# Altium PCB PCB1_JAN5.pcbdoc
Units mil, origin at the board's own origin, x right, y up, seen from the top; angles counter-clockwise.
Board outline 1805 x 855 mil, 2 copper layers (Top Layer, Bottom Layer); 70 components, 53 nets, 260 pads, 40 vias.
Unrouted connection lines stored in the file: 8.
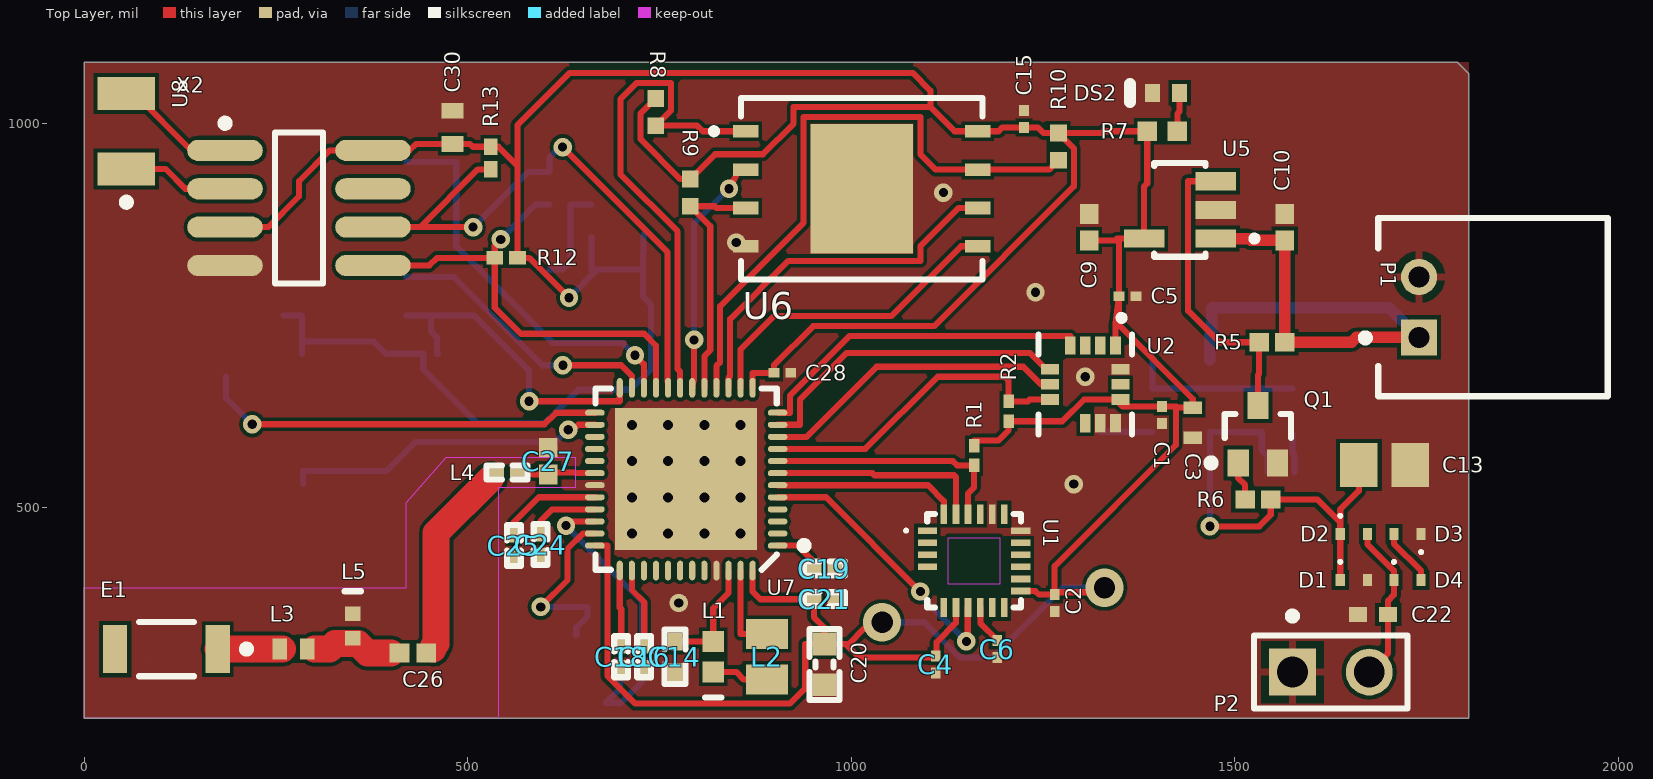
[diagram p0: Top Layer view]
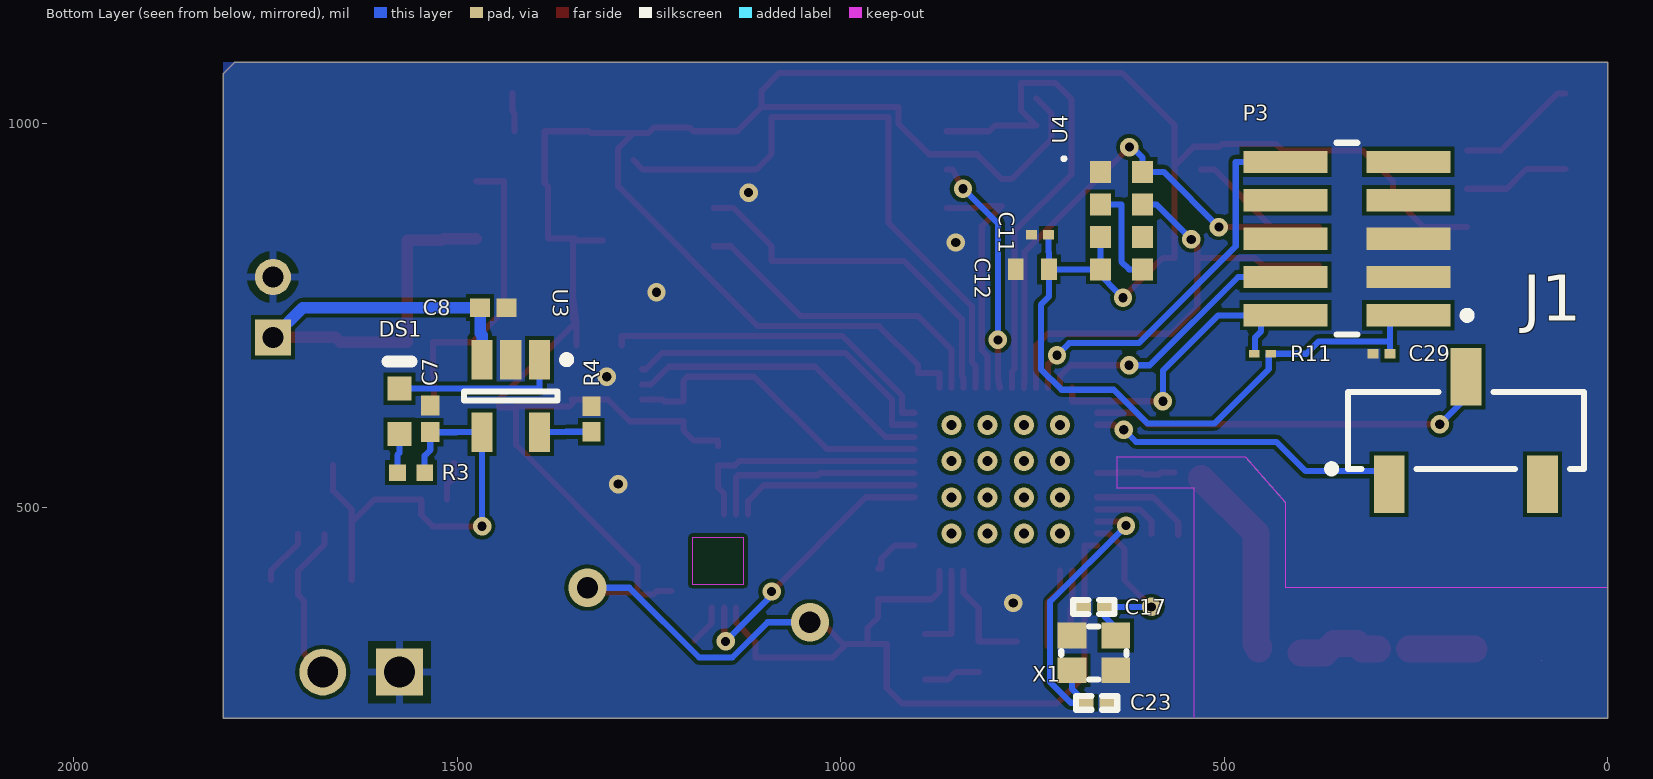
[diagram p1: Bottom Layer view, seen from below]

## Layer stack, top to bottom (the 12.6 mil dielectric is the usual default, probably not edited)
Top Solder: solder mask 0.4, Solder Resist, Dk 3.5
Top Layer: signal copper 1.4
Dielectric 1: dielectric 12.6, FR-4, Dk 4.8
Bottom Layer: signal copper 1.4
Bottom Solder: solder mask 0.4, Solder Resist, Dk 3.5

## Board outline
0,225 0,1080 1790,1080 1805,1065 1805,225
cut-out: 86.74,300.19

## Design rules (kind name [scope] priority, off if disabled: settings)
Clearance CPWG [InNet('RF')] p1: gap=5 ignorepadtopadclearanceinfootprint=TRUE // RF
Clearance [All] p2: gap=5 ignorepadtopadclearanceinfootprint=TRUE except(10: Via-Via)
HoleSize [All] p1: absolutevalues=TRUE maxlimit=100 minlimit=0.6 maxpercent=80.000 minpercent=20.000
MinimumSolderMaskSliver [All] p1: minsoldermaskwidth=5
PolygonConnect PolygonConnect_5 [All vs IsNamedPolygon('Top Layer-GND')] p1: thpad.connectstyle=Relief thpad.reliefconductorwidth=10 thpad.reliefentries=4 thpad.polygonreliefangle="90 Angle" thpad.airgapwidth=10 smdpad.connectstyle=Direct smdpad.reliefconductorwidth=10 smdpad.reliefentries=4 smdpad.polygonreliefangle="90 Angle" smdpad.airgapwidth=10 via.connectstyle=Direct via.reliefconductorwidth=10 via.reliefentries=4 via.polygonreliefangle="90 Angle" via.airgapwidth=10
PolygonConnect PolygonConnect_4 [All vs IsNamedPolygon('Bottom Layer-GND')] p2: thpad.connectstyle=Relief thpad.reliefconductorwidth=10 thpad.reliefentries=4 thpad.polygonreliefangle="90 Angle" thpad.airgapwidth=10 smdpad.connectstyle=Direct smdpad.reliefconductorwidth=10 smdpad.reliefentries=4 smdpad.polygonreliefangle="90 Angle" smdpad.airgapwidth=10 via.connectstyle=Direct via.reliefconductorwidth=10 via.reliefentries=4 via.polygonreliefangle="90 Angle" via.airgapwidth=10
PolygonConnect PolygonConnect_3 [All vs IsNamedPolygon('Top Layer-GND')] p3: thpad.connectstyle=Relief thpad.reliefconductorwidth=10 thpad.reliefentries=4 thpad.polygonreliefangle="90 Angle" thpad.airgapwidth=10 smdpad.connectstyle=Relief smdpad.reliefconductorwidth=10 smdpad.reliefentries=4 smdpad.polygonreliefangle="90 Angle" smdpad.airgapwidth=10 via.connectstyle=Direct via.reliefconductorwidth=10 via.reliefentries=4 via.polygonreliefangle="90 Angle" via.airgapwidth=10
PolygonConnect PolygonConnect_2 [All vs IsNamedPolygon('Bottom Layer-GND')] p4: thpad.connectstyle=Relief thpad.reliefconductorwidth=10 thpad.reliefentries=4 thpad.polygonreliefangle="90 Angle" thpad.airgapwidth=10 smdpad.connectstyle=Direct smdpad.reliefconductorwidth=10 smdpad.reliefentries=4 smdpad.polygonreliefangle="90 Angle" smdpad.airgapwidth=10 via.connectstyle=Relief via.reliefconductorwidth=10 via.reliefentries=4 via.polygonreliefangle="90 Angle" via.airgapwidth=10
PolygonConnect PolygonConnect_1 [All vs IsNamedPolygon('Top Layer-GND')] p5: thpad.connectstyle=Relief thpad.reliefconductorwidth=10 thpad.reliefentries=4 thpad.polygonreliefangle="90 Angle" thpad.airgapwidth=10 smdpad.connectstyle=Direct smdpad.reliefconductorwidth=10 smdpad.reliefentries=4 smdpad.polygonreliefangle="90 Angle" smdpad.airgapwidth=10 via.connectstyle=Relief via.reliefconductorwidth=10 via.reliefentries=4 via.polygonreliefangle="90 Angle" via.airgapwidth=10
PolygonConnect [All] p6: connectstyle=Relief reliefconductorwidth=10 reliefentries=4 polygonreliefangle="90 Angle" airgapwidth=10
RoutingVias [All] p1: holewidth=12 width=24 viastyle="Through Hole" minholewidth=12 minwidth=24 maxholewidth=12 maxwidth=24
SilkToSilkClearance [All] p1: silktosilkclearance=7
SilkToSolderMaskClearance [IsPad] p1: minsilkscreentomaskgap=5 clearancetoexposedcopper=TRUE
SolderMaskExpansion [All] p1: expansion=4
Width RF2 [InNet('NetE1_1')] p1: maxlimit=35 minlimit=35 preferedwidth=35 minimp=50.000000 maximp=50.000000 favimp=50.000000
Width RF1 [InNet('NetC26_1')] p2: maxlimit=35 minlimit=35 preferedwidth=35 minimp=50.000000 maximp=50.000000 favimp=50.000000
Width RF [InNet('RF')] p3: maxlimit=35 minlimit=35 preferedwidth=35 minimp=50.000000 maximp=50.000000 favimp=50.000000
Width VBAT [InNet('VBAT')] p4: maxlimit=15 minlimit=15 preferedwidth=15 minimp=50.000000 maximp=50.000000 favimp=50.000000
Width [All] p5: maxlimit=8 minlimit=8 preferedwidth=8 minimp=50.000000 maximp=50.000000 favimp=50.000000
26 further rules are at their usual default settings.

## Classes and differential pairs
component class "SimPL_IMU_v1_1 _JAN5": C14 C15 C16 C17 C18 C19 C20 C21 C23 C24 C25 C26 C27 C28 C29 C30 E1 J1 L1 L2 L3 L4 L5 P3 R8 R9 R10 R11 R12 R13 U6 U7 U8 X1 X2
component class SimPL_IMU_v1_0_JAN5: C1 C2 C3 C4 C5 C6 C7 C8 C9 C10 C11 C12 C13 C22 D1 D2 D3 D4 DS1 DS2 P1 P2 Q1 R1 R2 R3 R4 R5 R6 R7 U2 U3 U4 U5

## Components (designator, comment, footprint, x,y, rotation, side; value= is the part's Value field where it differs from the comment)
C1 "0.1uF" CAPC0603X33X15LL03T05 1405,620 r90 top
C2 "0.1uF" CAPC0603X33X15LL03T05 1265,375 r90 top
C3 "1.0uF" CAPC1005X70X10LL20T00 1445,610 r90 top
C4 "0.1uF" CAPC0603X33X15LL03T05 1110,295 r90 top
C5 "0.1uF" CAPC0603X33X15LL03T05 1360,775 r180 top
C6 "0.1uF" CAPC0603X33X15LL03T05 1190,315 r90 top
C7 "4.7uF" CAPC1005X55X25NL05T10 1535,615 r270 bottom
C8 "4.7uF" CAPC1005X55X25NL05T10 1452.68,760 r0 bottom
C9 "1uF" CAPC1005X55X25NL05T10 1310,865 r270 top
C10 "1uF" CAPC1005X55X25NL05T10 1565,865 r270 top
C11 "0.1uF" CAPC0603X33X15LL03T05 740,855 r180 bottom
C12 "2.2uF" CAPC1005X70X10NL20T00 750,810 r180 bottom
C13 "GRM21BR60J226ME39L" CAPC2013X140X45NL15T25 1695,555 r180 top
C14 "1.0µF" CAPC1005X04L 770,305 r90 top
C15 "0.1uF" CAPC0603X33X15LL03T05 1225,1006.02 r270 top
C16 "12pF" CAPC0603X03L 730,305 r90 top
C17 "12pF" CAPC0603X03L 670,370 r180 bottom
C18 "12pF" CAPC0603X03L 700,305 r90 top
C19 "100nF" CAPC0603X03L 965,420 r0 top
C20 "4.7µF" CAPC1608X06L 965,295 r270 top
C21 "100nF" CAPC0603X03L 965,380 r0 top
C22 "6.8nF" 0402 1680,360 r180 top
C23 "12pF" CAPC0603X03L 666.22,245 r0 bottom
C24 "100pF" CAPC0603X03L 595,451.22 r270 top
C25 "100pF" CAPC0603X03L 560,450 r90 top
C26 "1.0pF" CAPC1005X55X25NL05T10 428.58,309.96 r0 top
C27 "1.0pF" CAPC1005X55X25NL05T10 605,560 r270 top
C28 "0.1uF" CAPC0603X33X15LL03T05 910,675 r180 top
C29 "02016D104KAT2A" CAPC0603X33X15LL03T05 295,700 r180 bottom
C30 "TACK225M006QTA" CAPC1005X70X10NL20T00 480,995 r270 top
D1 "NSR0140P2T5G" ONSC-SOD-923-2-514AA-01_D_V 1655,405 r0 top
D2 "NSR0140P2T5G" ONSC-SOD-923-2-514AA-01_D_V 1655,465 r0 top
D3 "NSR0140P2T5G" ONSC-SOD-923-2-514AA-01_D_V 1725,465 r180 top
D4 "NSR0140P2T5G" ONSC-SOD-923-2-514AA-01_D_V 1725,405 r0 top
DS1 "HSMH-C190" AVAG-HSMX-C190_V 1575,625 r90 bottom
DS2 "SML-P11MTT86" ROHM-SML-P11MT_V 1410.24,1040 r180 top
E1 "2450AT18A100E" JT-2450AT18A100-2_V 107.25,315 r180 top
J1 "SSM-103-F-SV" SMTC-SSM-103-X-SV 185,600 r180 bottom
L1 "15nH" INDC1005X55X25ML05T10_A 820,305 r90 top
L2 "10uH" MURA-IND0805_L 890,305 r270 top
L3 "3.9nH" *INDC1006X60N 272.83,315 r180 top
L4 "3.3nH" INDC0603X03L 551.22,545 r180 top
L5 "2.7nH" INDC1005X55X25LL05T10_A 350,345 r270 top
P1 "Battery Header" JST-S2B-PH-K-S_V 1836.46,760.63 r90 top
P2 "2pin header" AMPH-68000-102HLF_V 1625,285 r0 top
P3 "FTSH-105-01-L-DV-K-TR" SMTC-FTSH-105-01-L-DV-K_V 340,850 r90 bottom
Q1 "BSS138W-7-F" DIOD-SOT323-3_V 1530,595 r90 top
R1 "10k" RESC0603X26X15NL03T05 1160,567.2 r90 top
R2 "10k" RESC0603X26X15NL03T05 1205,625 r270 top
R3 "330" RESC1005X40X25NL05T05 1560,545 r180 bottom
R4 "2.2K" RESC1005X40X25NL10T10 1325,615 r270 bottom
R5 "2.2k" RESC1005X40X25NL10T10 1548.27,715 r0 top
R6 "2.2k" RESC1005X40X25NL10T10 1530,510 r0 top
R7 "330" RESC1005X40X25ML05T05 1405.32,990 r180 top
R8 "10k" RESC1005X40X25NL05T05 745,1015 r90 top
R9 "10k" RESC1005X40X25NL05T05 790,910 r90 top
R10 "10k" RESC1005X40X25NL05T05 1270,970 r90 top
R11 "ERJ-1GEJ104C" RESC0603X26X15LL03T05 450,700 r0 bottom
R12 "2.2K" RESC0603X28X15ML05T05 550,825 r0 top
R13 "2.2K" RESC0603X28X15ML05T05 530,955 r90 top
U1 "ICM-20649" *QFN40P300X300X95-24N 1160,430 r0 top
U2 "ADXL372BCCZ-RL7" *PQFN50P322X300X114-16N 1305,660 r270 top
U3 "MCP73831T-2ATI/OT" SOT-23-OT5_M 1430,645 r270 bottom
U4 "VCNL4040M3OE" *VISHAY_VCNL4040_4X2X1.1 633.93,873.48 r180 bottom
U5 "AP2112K-3.3TRG1" *SOT95P285X140-5N 1428.35,887.4 r180 top
U6 "MT25QL256ABA1EW9-0SIT" *SON127P600X800X80-9N 1013.62,915 r0 top
U7 "nRF52832-QFAA" QFN40P600X600X90-48N 784.73,536.46 r180 top
U8 "DS1388Z-33+T&R" S8+4_M 280,890 r0 top
X1 "32MHz" BT-XTAL_2016 670,310 r180 bottom
X2 "32.768KHz-T" ABRA-ABS07-2_V 55,990 r90 top

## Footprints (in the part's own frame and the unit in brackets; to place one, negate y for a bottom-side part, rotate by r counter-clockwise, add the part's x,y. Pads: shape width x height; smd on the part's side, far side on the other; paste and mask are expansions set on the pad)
0402 [mm] "Chip Capacitor, Body 1.0x0.5mm, IPC High Density"
  rect 0.6x0.5 smd: 1(-0.5,0) 2(0.5,0)
  body extent -0.55,-0.3 0.55,0.3, height 1.3
*INDC1006X60N [mm]
  rect 0.49x0.7 smd: 1(-0.453,0) 2(0.453,0)
*PQFN50P322X300X114-16N [mm]
  rect 0.6x0.35 smd: 1(-1.285,1) 2(-1.285,0.5) 3(-1.285,0) 4(-1.285,-0.5) 11(1.285,0) 12(1.285,0.5) 13(1.285,1)
  rect 0.6x0.35 on Top Overlay: 5(-1.285,-1) 9(1.285,-1) 10(1.285,-0.5)
  rect 0.35x0.6 smd: 6(-0.5,-1.165) 7(0,-1.165) 8(0.5,-1.165) 14(0.5,1.165) 15(0,1.165) 16(-0.5,1.165)
  silkscreen extent -2.3,-1.55 1.65,1.55
*QFN40P300X300X95-24N [mm]
  rect 0.64x0.22 smd: 1(-1.545,1) 2(-1.545,0.6) 3(-1.545,0.2) 4(-1.545,-0.2) 13(1.545,-1) 14(1.545,-0.6) 15(1.545,-0.2) 16(1.545,0.2) 17(1.545,0.6) 18(1.545,1)
  rect 0.64x0.22 on Top Overlay: 5(-1.545,-0.6) 6(-1.545,-1)
  rect 0.22x0.64 smd: 7(-1,-1.545) 8(-0.6,-1.545) 9(-0.2,-1.545) 10(0.2,-1.545) 11(0.6,-1.545) 12(1,-1.545) 19(1,1.545) 20(0.6,1.545) 21(0.2,1.545) 22(-0.2,1.545) 23(-0.6,1.545) 24(-1,1.545)
  Keep-Out Layer region: -0.85,0.77 0.85,0.77 0.85,-0.77 -0.85,-0.77
  Keep-Out Layer region: -0.85,0.77 0.85,0.77 0.85,-0.77 -0.85,-0.77
  Keep-Out Layer region: -0.85,0.77 0.85,0.77 0.85,-0.77 -0.85,-0.77
  Keep-Out Layer region: -0.85,0.77 0.85,0.77 0.85,-0.77 -0.85,-0.77
  Keep-Out Layer region: -0.85,0.77 0.85,0.77 0.85,-0.77 -0.85,-0.77
  Keep-Out Layer region: -0.85,0.77 0.85,0.77 0.85,-0.77 -0.85,-0.77
  silkscreen extent -2.3,-1.55 1.55,1.55
*SON127P600X800X80-9N [mm]
  rect 0.84x0.42 smd: 1(-3.845,1.905) 2(-3.845,0.635) 3(-3.845,-0.635) 4(-3.845,-1.905) 5(3.845,-1.905) 6(3.845,-0.635) 7(3.845,0.635) 8(3.845,1.905)
  rect 3.4x4.3 smd: 9(0,0)
  silkscreen extent -4.99,-3 4,3
*SOT95P285X140-5N [mm]
  rect 1.35x0.6 smd: 1(-1.185,0.95) 2(-1.185,0) 3(-1.185,-0.95) 5(1.185,0.95)
  rect 1.35x0.6 on Top Overlay: 4(1.185,-0.95)
  silkscreen extent -2.57,-1.55 0.85,1.55
*VISHAY_VCNL4040_4X2X1.1 [mm]
  rect 0.7x0.725 smd: 1(-0.7,1.612) 2(-0.7,0.538) 3(-0.7,-0.537) 4(-0.7,-1.612) 5(0.7,-1.612) 6(0.7,-0.537) 7(0.7,0.538) 8(0.7,1.612)
  silkscreen extent -1.96,2 -1.86,2.1
ABRA-ABS07-2_V [mm] "Hand Drawn, 2-Leads, Body 3.2x1.5mm, Pitch 2.5mm"
  rect 1.1x1.9 smd: 1(-1.25,0) 2(1.25,0)
  silkscreen extent -2.47,-0.13 -2.23,0.12, body extent -1.6,-0.75 1.6,0.75, height 0.9
AMPH-68000-102HLF_V [mm] "THD, 2-Leads, Body 5.08x2.41mm, Pitch 2.54mm"
  rect 1.55x1.55 hole 1.02: 1(-1.27,0)
  round 1.55 hole 1.02: 2(1.27,0)
  silkscreen extent -2.54,-1.2 2.54,1.98, body extent -2.54,-1.2 2.54,1.2, height 8.38
AVAG-HSMX-C190_V [mm] "SMD, 2-Leads, Body 1.6x0.8mm, Height 0.9mm"
  rect 0.8x0.8 smd: 1(-0.75,0) 2(0.75,0)
  silkscreen extent 1.65,-0.4 1.65,0.4, body extent -0.8,-0.4 0.8,0.4, height 0.9
BT-XTAL_2016 [mm]
  rect 0.95x0.85 smd: 1(-0.725,-0.575) 2(0.725,-0.575) 3(0.725,0.575) 4(-0.725,0.575)
  silkscreen extent -1.08,-0.88 1.08,0.88, body extent -1.05,-0.85 1.05,0.85, height 0.56
CAPC0603X03L [mm]
  rect 0.5x0.3 smd: 1(-0.35,0) 2(0.35,0)
  silkscreen extent -0.68,-0.23 0.68,0.23, body extent -0.3,-0.15 0.3,0.15, height 0.3
CAPC0603X33X15LL03T05 [mm] "Chip Capacitor, 2-Leads, Body 0.60x0.30mm, IPC High Density"
  rect 0.36x0.32 smd: 1(-0.28,0) 2(0.28,0)
  body extent -0.32,-0.17 0.32,0.17, height 0.33
CAPC1005X04L [mm]
  rect 0.6x0.5 smd: 1(-0.5,0) 2(0.5,0)
  silkscreen extent -0.9,-0.35 0.9,0.35, body extent -0.51,-0.25 0.51,0.25, height 0.5
CAPC1005X55X25NL05T10 [mm] "Chip Capacitor, 2-Leads, Body 1.00x0.50mm, IPC Medium Density"
  rect 0.66x0.62 smd: 1(-0.44,0) 2(0.44,0)
  body extent -0.53,-0.28 0.53,0.27, height 0.55
CAPC1005X70X10LL20T00 [mm] "Chip Capacitor, 2-Leads, Body 1.00x0.50mm, IPC High Density"
  rect 0.42x0.62 smd: 1(-0.5,0) 2(0.5,0)
  body extent -0.6,-0.35 0.6,0.35, height 0.7
CAPC1005X70X10NL20T00 [mm] "Chip Capacitor, 2-Leads, Body 1.00x0.50mm, IPC Medium Density"
  rect 0.52x0.72 smd: 1(-0.55,0) 2(0.55,0)
  body extent -0.6,-0.35 0.6,0.35, height 0.7
CAPC1608X06L [mm]
  rect 0.75x0.8 smd: 1(-0.675,0) 2(0.675,0)
  silkscreen extent -1.17,-0.5 1.18,0.5, body extent -0.8,-0.43 0.8,0.43, height 0.8
CAPC2013X140X45NL15T25 [mm] "Chip Capacitor, 2-Leads, Body 2.00x1.25mm, IPC Medium Density"
  rect 1.25x1.45 smd: 1(-0.85,0) 2(0.85,0)
  body extent -1.08,-0.7 1.07,0.7, height 1.4
DIOD-SOT323-3_V [mm] "SOT323, 3-Leads, Body 2.2x1.35mm, Pitch 0.65mm"
  rect 0.9x0.7 smd: 1(-0.95,0.65) 2(-0.95,-0.65) 3(0.95,0)
  silkscreen extent -1.07,-1.1 0.67,1.67, body extent -1.1,-1.1 1.1,1.1, height 1.07
INDC0603X03L [mm]
  rect 0.5x0.3 smd: 1(-0.35,0) 2(0.35,0)
  silkscreen extent -0.68,-0.23 0.68,0.23, body extent -0.31,-0.16 0.31,0.16, height 0.26
INDC1005X55X25LL05T10_A [mm] "Chip Inductor, 2-Leads, Body 1.05x0.55mm, IPC High Density"
  rect 0.49x0.52 smd: 1(-0.405,0) 2(0.405,0)
  silkscreen extent -1.15,-0.27 -1.15,0.27, body extent -0.52,-0.28 0.53,0.28, height 0.55
INDC1005X55X25ML05T10_A [mm] "Chip Inductor, 2-Leads, Body 1.05x0.55mm, IPC Low Density"
  rect 0.69x0.72 smd: 1(-0.505,0) 2(0.505,0)
  silkscreen extent -1.35,-0.27 -1.35,0.27, body extent -0.52,-0.28 0.53,0.28, height 0.55
JST-S2B-PH-K-S_V [mm] "THD, 2-Leads, Body 7.6x5.9mm, Pitch 2mm"
  rect 1.2x1.2 hole 0.7: 1(-1,2.45)
  round 1.2 hole 0.7: 2(1,2.45)
  silkscreen extent -2.95,-3.8 2.95,4.35, body extent -2.95,-3.8 2.95,3.8, height 4.8
JT-2450AT18A100-2_V [mm] "Chip Antenna, 2-Leads, Body 3.4x1.8mm"
  rect 0.8x1.6 smd: 1(-1.7,0) 2(1.7,0)
  silkscreen extent -2.78,-0.9 0.91,0.9, body extent -1.7,-0.9 1.7,0.9, height 1.4
MURA-IND0805_L [mm] "Chip Inductor, 2-Leads, Body 2.2x1.45mm, IPC High Density"
  rect 0.99x1.39 smd: 1(-0.755,0) 2(0.755,0)
  body extent -1.1,-0.72 1.1,0.72, height 1.45
ONSC-SOD-923-2-514AA-01_D_V [mm] "SOD, 2-Leads, Body 0.8x0.6mm"
  rect 0.3x0.4 smd: 1(-0.45,0) 2(0.45,0)
  silkscreen extent -0.5,0.55 -0.4,0.65, body extent -0.4,-0.3 0.4,0.3, height 0.43
QFN40P600X600X90-48N [mm]
  oval 0.65x0.2 smd: 1(-3.025,2.2) 2(-3.025,1.8) 3(-3.025,1.4) 4(-3.025,1) 5(-3.025,0.6) 6(-3.025,0.2) 7(-3.025,-0.2) 8(-3.025,-0.6) 9(-3.025,-1) 10(-3.025,-1.4) 11(-3.025,-1.8) 12(-3.025,-2.2) 25(3.025,-2.2) 26(3.025,-1.8) 27(3.025,-1.4) 28(3.025,-1) 29(3.025,-0.6) 30(3.025,-0.2) 31(3.025,0.2) 32(3.025,0.6) 33(3.025,1) 34(3.025,1.4) 35(3.025,1.8) 36(3.025,2.2)
  oval 0.2x0.65 smd: 13(-2.2,-3.025) 14(-1.8,-3.025) 15(-1.4,-3.025) 16(-1,-3.025) 17(-0.6,-3.025) 18(-0.2,-3.025) 19(0.2,-3.025) 20(0.6,-3.025) 21(1,-3.025) 22(1.4,-3.025) 23(1.8,-3.025) 24(2.2,-3.025) 37(2.2,3.025) 38(1.8,3.025) 39(1.4,3.025) 40(1,3.025) 41(0.6,3.025) 42(0.2,3.025) 43(-0.2,3.025) 44(-0.6,3.025) 45(-1,3.025) 46(-1.4,3.025) 47(-1.8,3.025) 48(-2.2,3.025)
  rect 4.7x4.7 smd: 49(0,0)
  silkscreen extent -4.03,-3 3,3, body extent -3.02,-3.02 3.02,3.02, height 0.86
RESC0603X26X15LL03T05 [mm] "Chip Resistor, 2-Leads, Body 0.60x0.30mm, IPC High Density"
  rect 0.35x0.25 smd: 1(-0.275,0) 2(0.275,0)
  body extent -0.32,-0.16 0.31,0.17, height 0.26
RESC0603X26X15NL03T05 [mm] "Chip Resistor, 2-Leads, Body 0.60x0.30mm, IPC Medium Density"
  rect 0.45x0.35 smd: 1(-0.325,0) 2(0.325,0)
  body extent -0.32,-0.16 0.32,0.17, height 0.26
RESC0603X28X15ML05T05 [mm] "Chip Resistor, 2-Leads, Body 0.60x0.30mm, IPC Low Density"
  rect 0.55x0.45 smd: 1(-0.375,0) 2(0.375,0)
  body extent -0.33,-0.17 0.33,0.18, height 0.28
RESC1005X40X25ML05T05 [mm] "Chip Resistor, 2-Leads, Body 1.00x0.50mm, IPC Low Density"
  rect 0.65x0.65 smd: 1(-0.5,0) 2(0.5,0)
  body extent -0.53,-0.27 0.53,0.28, height 0.4
RESC1005X40X25NL05T05 [mm] "Chip Resistor, 2-Leads, Body 1.00x0.50mm, IPC Medium Density"
  rect 0.55x0.55 smd: 1(-0.45,0) 2(0.45,0)
  body extent -0.53,-0.27 0.53,0.28, height 0.4
RESC1005X40X25NL10T10 [mm] "Chip Resistor, 2-Leads, Body 1.00x0.50mm, IPC Medium Density"
  rect 0.65x0.6 smd: 1(-0.425,0) 2(0.425,0)
  body extent -0.55,-0.3 0.55,0.3, height 0.4
ROHM-SML-P11MT_V [mm] "SMD, 2-Leads, Body 0.6x1mm"
  rect 0.5x0.6 smd: 1(-0.45,0) 2(0.45,0)
  silkscreen extent 1.2,-0.3 1.2,0.3, body extent -0.5,-0.3 0.5,0.3, height 0.25
S8+4_M [mm] "SOIC, 8-Leads, Body 4.9x3.9mm, Pitch 1.27mm, IPC Low Density"
  oval 2.5x0.7 smd: 1(-2.45,1.905) 2(-2.45,0.635) 3(-2.45,-0.635) 4(-2.45,-1.905) 5(2.45,-1.905) 6(2.45,-0.635) 7(2.45,0.635) 8(2.45,1.905)
  silkscreen extent -2.57,-2.5 0.8,2.93, body extent -2,-2.5 2,2.5, height 1.75
SMTC-FTSH-105-01-L-DV-K_V [mm] "CONN, 10-Leads, Body 6.35x3.43mm, Pitch 1.27mm"
  rect 0.74x2.79 smd: 1(-2.54,-2.035) 2(-2.54,2.035) 3(-1.27,-2.035) 4(-1.27,2.035) 5(0,-2.035) 6(0,2.035) 7(1.27,-2.035) 8(1.27,2.035) 9(2.54,-2.035) 10(2.54,2.035)
  silkscreen extent -3.17,-4.1 3.17,0.34, body extent -3.17,-2.92 3.18,2.92, height 6.12
SMTC-SSM-103-X-SV [mm] "C.L. Surface Mount Socket Strip, 3 Pins, Vertical, 2.54 mm Pitch, Female"
  rect 1.02x1.905 smd: 1(-2.54,-1.777) 2(0,1.777) 3(2.54,-1.777)
  silkscreen extent -4.57,-1.39 3.91,1.27, body extent -3.81,-2.29 3.81,2.29, height 7.42
SOT-23-OT5_M [mm] "SOT23, 5-Leads, Body 2.9x1.7mm, Pitch 0.95mm, Lead Span 2.8mm, IPC Low Density"
  rect 1.3x0.7 smd: 1(-1.2,0.95) 2(-1.2,0) 3(-1.2,-0.95) 4(1.2,-0.95) 5(1.2,0.95)
  silkscreen extent -1.32,-1.55 0.15,1.97, body extent -0.9,-1.55 0.9,1.55, height 1.45

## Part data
C1 C2 C4 C5 C6 C11 C15 C28: library part CMP-2010-01264-1, Manufacturer=Murata, Part Number=GRM033R61A104KE15D
C3: library part CMP-2008-00066-1, Manufacturer="AVX Interconnect / Elco", Part Number=TACK105M010QTA
C7 C8: library part CMP-2008-04549-1, Manufacturer=Murata, Part Number=GRM155R60J475ME47D
C9 C10: library part CMP-2008-04556-1, Manufacturer=Murata, Part Number=GRM155R61A105KE15D
C12: library part CMP-2008-00070-1, Manufacturer="AVX Interconnect / Elco", Part Number=TACK225M006QTA
C13: library part CMP-2007-03385-1, Manufacturer=Murata
C14: library part C0402-1µ0, "Capacitor, X5R, ±5%", Part Number=C0402C105K9PACTU
C16: library part C0201-12p, "Capacitor, NP0, ±2%", Part Number=CC0201JRNPO8BN120
C17 C18 C23: library part C0201-12p, "Capacitor, NP0, ±2%", Manufacturer Part Number=CC0201JRNPO8BN120
C19 C21: library part C0201-100n, "Capacitor, X7R, ±10%", Manufacturer Part Number=CC0201KRX5R5BB104
C20: library part C0603-4µ7, "Capacitor, X5R, ±10%", Manufacturer Part Number=C0603C475K9PACTU
C22: library part 0.1UF-0402-16V-10%, "0.1µF ceramic capacitors    A capacitor is a passive two-terminal electrical component used to store electrical energy temporarily in an electric field.", Part Number=CC0402KRX7R9BB682
C24 C25: library part C0201-100p, "Capacitor, NP0, ±5%", Manufacturer Part Number=CC0201JRNPO9BN101
C26 C27: library part CMP-2008-03808-1, Manufacturer=Murata, Part Number=GJM1555C1H1R0BB01D
C29: library part CMP-2010-00159-1, Manufacturer="AVX Interconnect / Elco"
C30: library part CMP-2008-00070-1, Manufacturer="AVX Interconnect / Elco"
D1 D2 D3 D4: library part CMP-1055-00493-1, "Schottky Barrier Diode, 2-Pin SOD-923, Pb-Free, Tape and Reel", Manufacturer="On Semiconductor"
DS1: library part CMP-1744-00004-1, "LED Uni-Color Red, 65 mW, 20 mA, -40 to 85 degC, 2-Pin SMD, RoHS, Tape and Reel", Current Rating="1 A", Max Operating Temperature="85 degC", Min Operating Temperature="-30 degC", Package Quantity=2000
DS2: library part CMP-2000-07126-1, "LED Green, 54 mW, 20 mA, -40 to 85 degC, 2-Pin SMD, RoHS, Tape and Reel", Color=Green, Forward (Drive) Current=20mA, Forward Voltage=1.9V, Manufacturer="Lite-On Inc.", Manufacturer Part Number=LTST-C170KGKT, Package Description="2-Pin Surface Mount Device, Body 0.6 x 1 mm", Package Reference=SML-P11MT
E1: library part CMP-2000-05167-1, "Ceramic Antenna, 2.45 GHZ, 2 W, -40 to 125 degC, 2-Pin SMD, RoHS, Tape and Reel", Manufacturer="Johanson Technology", Maximum Frequency=2500MHz, Minimum Frequency=2400MHz, Package=2Case18-4
J1: library part CMP-1023-00202-1, "Tiger Claw(TM) Surface Mount Socket, Vertical, -55 to 125 degC, 2.54 mm Pitch, 3-Pin, Female, RoHS", Manufacturer=Samtec, Temperature Range="-55 to 125 degC"
L1: library part CMP-2100-03652-1, "Chip Inductor, 15 nH, +/- 5%, 100 MHz, -55 to 125 degC, 0402 (1005 Metric), RoHS, Paper Tape", Case/Package=0402, Case Code (Metric)=1005, Current Rating=300mA, DC Resistance (DCR)=320mOhm, Inductance=15nh, Manufacturer=Murata, Manufacturer Part Number=HK100515NJ-T, Max Operating Temperature=125degC, Min Operating Temperature=-55degC, Package Description="2-Pin Surface Mount Device, Body 1 x 0.5 mm", Package Quantity=10000, Self Resonant Frequency=2.5GHz, Test Frequency=100MHz, Tolerance=5%
L2: library part CMP-2000-06587-1, "Fixed Inductor, 10 uH, +/-20%, -55 to 125 degC, 2-Pin SMD (0805), RoHS, Tape and Reel", Case Size/Dimension=0805, DC Resistance=0.6, Inductance-Nom=10H, Manufacturer=Bourns, Manufacturer Part Number=CV201210-100K, Package Description="2-Pin Surface Mount Device, Body 2 x 1.25 mm", Package Reference=IND0805, Rated Current-Max=100mA, Tolerance (%)=20%
L3: library part MHQ1005P3N9CT000, "Inductor, 3.9nh, 0.2nh, 0.9a, 0402", Manufacturer Part Number=L-07C3N9SV6T, Package="1006 TDK"
L4: library part L0201-3n3, "High frequency chip inductor ±5%", Manufacturer=Murata, Manufacturer Part Number=LQP03TN3N3B02D
L5: library part CMP-2000-06580-1, "Chip Inductor, 2.7 nH, +/- 0.3 nH, 300 mA, -55 to 125 degC, 0402 (1005 Metric), RoHS, Tape and Reel", Current Rating=300mA, DC Resistance (DCR)=150mOhmMax, Frequency - Self Resonant=6GHz, Frequency - Test=100MHz, Manufacturer=Murata, Manufacturer Part Number=L-07C2N7SV6T, Operating Temperature=-55°C~125°C, Package / Case=0402(1005Metric), Package Description="2-Pin Surface Mount Device, Body 1 x 0.5 mm", Package Reference=0402, Q @ Freq=8@100MHz, Standard Package=10,000, Tolerance=±0.3nH
P1: library part CMP-1755-00004-1, "Male Header, Pitch 2 mm, 1 x 2 Position, Height 4.8 mm, Tail Length 3.4 mm, -25 to 85 degC, RoHS, Bulk", Capacitance="10 uF", Case\Package=Radial, Max Operating Temperature="85 degC", Min Operating Temperature="-40 degC", Package Quantity=200, Tolerance=20%, Voltage Rating="50 V"
P2: library part CMP-2000-05666-1, "Male Header, Pitch 2.54 mm, 1 x 2 Position, Height 8.38 mm, Tail Length 2.41 mm, RoHS, Bulk", Current Rating=3A, Flammability Rating=UL94V-0, Insulation Resistance=5000MOhms, Manufacturer=FCI, Operating Temperature Range=-65Cto+125C, Package Description="Male Header, Pitch 2.54 mm, 1 x 2 Position, Height 8.38 mm, Tail Length 2.41 mm", Package Reference=68000-102HLF, Voltage Rating=1.5kV
P3: library part CMP-2000-06293-1, "Male Header, Pitch 1.27 mm, 2 x 5 Position, Height 6.12 mm, -55 to 125 degC, RoHS, Tape and Reel", Manufacturer=Amphenol, Package Description="Male Header, Pitch 1.27 mm, 2 x 5 Position, Height 5.97 mm, Tail Length 4.32 mm", Package Reference=20021121-00010C4LF
Q1: library part CMP-2000-05968-1, "N-Channel Enhancement Mode Mosfet, 50 V, 200 mA, -55 to 150 degC, 6-Pin SOT-323, RoHS, Tape and Reel", Id - Continuous Drain Current=200mA, Manufacturer=DiodesIncorporated, Maximum Operating Temperature=+150C, Minimum Operating Temperature=-55C, Package / Case=SOT-323-3, Package Description="3-Pin Small Outline Transistor, Body 2 x 1.25 mm, Pitch 0.65 mm", Package Reference=SOT323, Pd - Power Dissipation=200mW, Rds On - Drain-Source Resistance=1.4Ohms, Vds - Drain-Source Breakdown Voltage=75V, Vgs - Gate-Source Voltage=20V
R1 R2: library part CMP-2004-02627-1, Manufacturer=Panasonic, Part Number=ERJ-1GEF1002C
R3: library part CMP-2002-08523-1, Manufacturer="Vishay Dale", Part Number=CRCW0402330RFKED
R4 R5 R6: library part CMP-2002-05881-1, Manufacturer=Panasonic, Part Number=ERA2AEB222X
R7: library part CMP-2002-01143-1, Manufacturer=Panasonic, Part Number=ERJ2RKF3300X
R8 R9 R10: library part CMP-2002-00607-3, "Chip Resistor, 10 KOhm, +/- 1%, 100 mW, -55 to 155 degC, 0402 (1005 Metric), RoHS, Tape and Reel", Case\/Package=0402, Case Code (Metric)=1005, Manufacturer="Basic Passives", Max Operating Temperature="155 degC", Min Operating Temperature="-55 degC", Package Quantity=10000, PartNumber=ERJ-2RKF1002X, Power Rating="100 mW", Resistance="10 KOhm", Tolerance=1%, Voltage Rating="50 V"
R11: library part CMP-2004-03147-1, Manufacturer=Panasonic
R12 R13: library part CMP-2004-00412-1, Manufacturer="Vishay Dale", Part Number=CRCW02012K20FNED
U1: "Wide-Range 6-Axis MEMS MotionTracking Device for Sports and High Impact Applications", Package="QFN-24 InvenSense"
U2: "Accelerometer Triple ±200g 2.5V 16-Pin LGA T/R", Package="LGA-16 Analog Devices"
U3: library part CMP-0133-00144-1, "Miniature Single-Cell, Fully Integrated Li-Ion, Li-Polymer Charge Management Controller, 4.2V, 5-Pin SOT-23, Industrial Temperature, Tape and Reel"
U4: "VCNL4040 Series 3.6 V 200 mm 16 Bit I2C SMT Proximity and Ambient Light Sensor", Package="SMD-8 Vishay"
U5: "AP2112 Series 0.6 A 3.3 V Fixed Output SMT LDO Linear Regulator - SOT23-5", Package="SOT-753 Diodes Inc."
U6: "NOR Flash Serial-SPI 3.3V 256Mbit 256M x 1bit 8-Pin WPDFN", Package="WDFN-8 Micron Technology"
U7: "Multi-protocol Bluetooth Low Energy, ANT and 2.4GHz proprietary system-on-chip", Manufacturer="Nordic Semiconductor"
U8: library part CMP-0254-00385-1, "I2C Real-Time Clock/Supervisor with Trickle Charger and 512 Byte EEPROM, 3.3V, 8-Pin SO, -40 to 85 degC, Pb-Free, Reel"
X1: library part XTAL_SMD2016_32MHz_8pF_Epson, "XTAL SMD 2016, 32MHz, Cl=8pF, Total Tol: ±40ppm", Manufacturer="ECS Inc.", Manufacturer Part Number=ECS-320-8-37B-CKY-TR, Supplier part number=171-2806
X2: library part CMP-0447-00001-2, "Crystal, 32.768 kHz, 12.5 pF, -40 to 85 degC, SMD Low Profile 3.2 x 1.5 x 0.9 mm, Tape and Reel", Equivalent Series Resistance (R1)="70 Kohm", Frequency="32.768 kHz", Frequency Tolerance @+25degC="+/- 20 ppm", Insulation Resistance (Min)="500 Mohm", Load Capacitance (CL)="12.5 pF", Manufacturer=Abracon, Operating Temperature="-40 to 85 degC", PartNumber=ABS07-32.768KHz-T, Q Value (Type)=30000, Shunt Capacitance (C0)="0.9 to 1.2 pF"

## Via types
v1: diameter 24, hole 12, Top Layer to Bottom Layer, 22 vias
v2: diameter 25.98, hole 12.99, Top Layer to Bottom Layer, 16 vias
v3: diameter 50, hole 28, Top Layer to Bottom Layer, 2 vias

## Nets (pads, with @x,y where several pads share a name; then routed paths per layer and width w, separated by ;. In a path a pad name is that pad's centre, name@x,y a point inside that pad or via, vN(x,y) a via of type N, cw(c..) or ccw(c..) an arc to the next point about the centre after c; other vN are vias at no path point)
+3V3: C1.2 C2.2 C3.2 C4.2 C5.2 C9.2 C11.2 C12.2 C15.2 C20.1 C21.1 C28.2 C29.2 C30.2 P3.1 R1.2 R2.2 R7.2 R8.2 R9.2 R10.2 R11.1 R12.2 R13.2 U1.8 U1.13 U2.1 U2.14 U4.3 U4.4 U5.5 U6.8 U7.13 U7.36 U7.48 U8.3 U8.8 | length 6360.5
  Top Layer w8: U8.3 240,865 280,905 280,925 320,965 U8.8 424,965 432.35,973.35 C30.2 503,973.35 506.58,969.76 R13.2 540,969.76 564.76,945 ; v1(632,773) 580,825 R12.2 564.76,945 ; U7.36 682,449.85 682,280 718,244 920,244 940,264 940,321.57 C20.1 ; R8.2 725,1012.72 725,980 777.28,927.72 R9.2 822.28,960 884.69,960 924.69,1000 924.69,1021.65 1103,1021.65 ; U7.48 871.35,390 881.35,380 C21.1 951.22,356.78 965,343 C20.1 ; U7.13 871.35,675 C28.2 898.98,684.95 950.02,736 1108,736 1290,918 1290,967.72 R10.2 ; v3(1040,350) 1031.96,341.96 1016.96,341.96 996.57,321.57 992.43,321.57 ; U1.8 1136.38,349.35 1111.02,324 1111.02,303.98 1010,304 992.43,321.57 ; R1.2 1160,587 1192,587 1205,600 R2.2@1205,612 ; R2.2 R2.2@1205,612 ; U1.13 1240,390.63 1244.61,386.02 C2.2 C2.2@1265,386.81 ; C9.2 1344,847.68 1346.32,850 1348.98,850 ; v3(1330,395) 1324.11,389.11 1267.3,389.11 C2.2@1265,386.81 ; U2.1 1344.37,740 1345.04,745.12 C5.2 ; U2.14 U2.14@1344.69,640.31 ; 564.76,945 564.76,997.76 633,1066 1080,1066 1103,1043 1103,1021.65 ; C20.1 992.43,321.57 ; 1103,1021.65 1134.65,990 U6.8 1192,990 1197,995 C15.2 1243,995 1250.28,987.72 R10.2 ; R2.2@1205,612 1275,612 1303.31,640.31 U2.14@1344.69,640.31 ; C2.2@1265,386.81 1265,423 1423,581 1423,631.02 ; R10.2 1326,987.72 1328.28,990 R7.2 1385.63,921.94 1381.69,918 U5.5 1348.98,850 ; U2.14@1344.69,640.31 1353.98,631.02 C1.2 1423,631.02 ; C5.2 1348.98,850 ; C5.2 1348.98,744.61 1345.17,740.8 1445,640.98 C3.2 1425.34,629.69 1424,631.02 1423,631.02
  Bottom Layer w8: P3.1 283.98,750 283.98,716 ; C29.2 283.98,716 ; v1(632,773) U4.4@669,810 ; U4.3 U4.4 U4.4@669,810 ; C11.2 728.98,832.63 728.35,832 C12.2 ; v3(1040,350) 1095.3,350 1141.3,304 1184.47,304 1275.47,395 v3(1330,395) ; 283.98,716 377,716 393,700 R11.1 442,700 442,680 513,609 600,609 644,653 712,653 739,680 739,764 728.35,774.65 C12.2 ; U4.4@669,810 C12.2
ACCEL_CS: R2.1 U2.8 U7.9 | length 424.6
  Top Layer w8: U7.9 1018.43,575.83 1112.58,669.98 1200.02,669.98 1205,665 R2.1 1230,637.8 1232.52,640.31 U2.8
ACCEL_MISO: U2.7 U7.10 | length 402.7
  Top Layer w8: U7.10 941.56,591.58 1032.96,682.98 1224.02,682.98 1247,660 U2.7
ACCEL_MOSI: U2.6 U7.11 | length 422.2
  Top Layer w8: U7.11 933,607.33 933,640.15 993.85,701 1232.68,701 1254,679.68 U2.6
ACCEL_SCLK: U2.4 U7.12 | length 448.4
  Top Layer w8: U7.12 919.88,623.07 919.88,645.42 997.46,723 1285.31,723 U2.4
CATHODE: U4.2 U4.5 | length 133.9
  Bottom Layer w8: U4.5 624,810 634,820 634,894.65 U4.2
COIL1: C22.1 D2.2 D4.1 P2.2 | length 207.7
  Top Layer w8: D2.2 1672.72,451.57 1707.28,417 D4.1 1707.28,385.6 1699.68,378 C22.1 1699.68,309.68 P2.2
DEC1: C19.1 U7.1 | length 67.3
  Top Layer w8: U7.1 930,449.85 947,432.85 947,420 C19.1
DEC2: C25.2 U7.32 | length 135.5
  Top Layer w8: C25.2 560,480 592.84,512.84 U7.32
DEC3: C24.1 U7.33 | length 94
  Top Layer w8: C24.1 595,482.09 610,497.09 U7.33@657,497.09 ; U7.33@657,497 U7.33@657,497.09 ; U7.33 U7.33@657,497.09
DEC4: C14.2 L1.2 U7.46 | length 150.8
  Top Layer w8: C14.2 794,324.68 794.2,324.88 L1.2 820,368.15 839.85,388 U7.46
GND: C1.1 C2.1 C3.1 C4.1 C5.1 C6.1 C7.1 C8.1 C9.1 C10.1 C11.1 C12.1 C13.1 C14.1 C15.1 C16.1 C17.1 C18.1 C19.2 C20.2 C21.2 C22.2 C23.1 C24.2 C25.1 C27.1 C28.1 C29.1 C30.1 D1.2 D3.1 DS2.2 L5.1 P1.2 P2.1 P3.3 P3.5 Q1.2 R4.1 U1.18 U1.20 U2.12 U2.13 U2.16 U3.2 U4.1 U5.2 U6.4 U6.9 U7.31 U7.45 U7.49 U8.4 X1.2 X1.4
  other v1: 775,375 1290,530 1305,670 1240,780 850,845 1120,910
GYRO_CS: R1.1 U1.22 U7.8 | length 325.4
  Top Layer w8: U7.8 1132.16,560.08 1137.84,554.41 R1.1 1160,525.87 1152.13,518 U1.22
GYRO_MISO: U1.9 U7.5 | length 372
  Top Layer w8: U7.5 967.16,512.84 v1(1090,390) ; v1(1150,325) 1151.8,326.8 1151.8,368.84 U1.9
  Bottom Layer w8: v1(1090,390) 1090,385.67 1095,380.67 1095,380 v1(1150,325)
GYRO_MOSI: U1.24 U7.6 | length 242.5
  Top Layer w8: U7.6 1019.79,528.59 1019.84,528.54 1100.05,528.54 1120.63,507.96 U1.24
GYRO_SCLK: U1.23 U7.7 | length 283
  Top Layer w8: U7.7 1027.2,544.33 1030,541.54 1134,541.54 1136.38,539.16 U1.23
I2C_SCL: R13.1 U4.8 U7.20 U8.6 | length 795.7
  Top Layer w8: U8.6 438,865 ; v1(507,865) 438,865 ; R13.1 513.24,940.24 438,865 ; v1@620,969.37 v1(623.63,969.37) 760.51,832.49 760.51,663.5 761.11,663.5 U7.20
  Bottom Layer w8: v1(507,865) 578.97,936.97 U4.8 606.37,955.75 v1@620,969.37
I2C_SDA: R12.1 U4.7 U7.21 U8.5 | length 623.1
  Top Layer w8: U8.5 450,815 460,825 R12.1 ; v1(543,849) 535.24,841.24 R12.1 ; U7.21 745.36,710.64 730,726 569.24,726 535.24,760 R12.1
  Bottom Layer w8: v1(543,849) 588.65,894.65 U4.7
MEM_CS: R8.1 U6.1 U7.19 | length 667.7
  Top Layer w8: U7.19 776.86,676.5 773.51,679.86 773.51,859.49 699,934 699,1032 720,1053 765,1053 765,1017.28 R8.1 799,997.28 806.28,990 U6.1
MEM_MISO: U6.5 U7.14 | length 415.1
  Top Layer w8: U7.14 855.6,705.6 899,749 1052,749 1143,840 U6.5
MEM_MOSI: U6.2 U7.18 | length 315.8
  Top Layer w8: U7.18 795,666.39 v1(795,718) ; v1@840,915 841,915 854,940 U6.2
  Bottom Layer w8: v1(795,718) 795,870 v1@840,915
  other v1: 840.5,915
MEM_SCLK: U6.6 U7.15 | length 484.5
  Top Layer w8: U7.15 839.85,668.35 842,670.5 842,745 918,821 1090,821 1090,840 1140,890 U6.6
MEM_SPI_HOLD: R10.1 U6.7 U7.16 | length 794.5
  Top Layer w8: U7.16 824.1,684 829,688.9 829,761.9 937.69,870.59 937.69,1008.65 1090,1008.65 1090,960 1110,940 U6.7 1257.72,940 R10.1
MEM_SPI_W: R9.1 U6.3 U7.17 | length 323.9
  Top Layer w8: U7.17 808.36,697 816,704.64 816,866.28 R9.1 821.85,892.28 824.14,890 U6.3
NetC6_2: C6.2 U1.10 | length 52.3
  Top Layer w8: U1.10 1168.2,368.84 1168.2,348.61 1190,326.81 C6.2
NetC16_2: C16.2 U7.38 | length 105.3
  Top Layer w8: U7.38 713.87,392 730,375.87 C16.2
NetC18_2: C18.2 U7.37 | length 99.4
  Top Layer w8: U7.37 698.12,368.88 700,367 C18.2
NetC26_1: C26.1 L3.1 L5.2 | length 107.9
  Top Layer w35: L3.1@300,315 320,315 327.03,322.03 350,322.03 357.03,322.03 369.1,309.96 C26.1@400,309.96
NetC27_2: C27.2 L4.1 U7.30 | length 102.8
  Top Layer w8: L4.1 583,545 585.32,542.68 C27.2 607.32,545 640,545 640.67,544.33 U7.30
NetD3_2: D3.2 D4.2 | length 74.7
  Top Layer w8: D3.2 1707.28,452.43 1742.72,417 D4.2
NetDS1_1: DS1.1 R3.1 | length 51.6
  Bottom Layer w8: DS1.1 1575,570.71 1577.72,568 R3.1
NetDS1_2: DS1.2 U3.1 | length 220.1
  Bottom Layer w8: U3.1 1392.6,654.53 DS1.2
NetDS2_1: DS2.1 R7.1 | length 51.2
  Top Layer w8: R7.1 1425,1013 1427.95,1015.95 DS2.1
NetE1_1: E1.1 L3.2 | length 84.5
  Top Layer w35: E1.1 174.37,315.19 254.81,315.19 L3.2 L3.2@258.52,315
NetL1_1: L1.1 L2.2 | length 74.1
  Top Layer w8: L1.1 850,285.12 859.84,275.28 L2.2
NetL2_1: L2.1 U7.47 | length 117
  Top Layer w8: U7.47 855.6,334.72 L2.1
NetP3_2: P3.2 R11.2 U7.24 | length 419.5
  Top Layer w8: v1(580,638) 698.12,638 U7.24
  Bottom Layer w8: P3.2 P3.2@452,750 ; R11.2 460,700 460,721 452,729 P3.2@452,750 ; v1(580,638) 580,678 508,750 P3.2@452,750
NetQ1_1: Q1.1 R6.1 | length 51.3
  Top Layer w8: Q1.1 1504.41,537.86 1513.27,529 R6.1
NetQ1_3: Q1.3 R5.1 U5.3 | length 397.6
  Top Layer w8: U5.3 1439,924.8 1439,756 1480,715 R5.1 1531.54,673.54 1530,672 Q1.3
NetR4_2: R4.2 U3.5 | length 67.8
  Bottom Layer w8: R4.2 1358,598.27 1358.51,597.76 U3.5
NetU8_1: U8.1 X2.2 | length 159.3
  Top Layer w8: X2.2 65,1039.21 139.21,965 U8.1
NetU8_2: U8.2 X2.1 | length 139.2
  Top Layer w8: X2.1 106,940.79 131.79,915 U8.2
nRESET: P3.10 U7.22 | length 514
  Top Layer w8: v1(718,698.03) 729.62,686.42 U7.22
  Bottom Layer w8: P3.10 485,950 485,840 611.16,713.84 702.2,713.84 v1(718,698.03)
P0.27: U7.39
P0.28/AIN4: U7.40
RF: C26.2 L4.2 | length 253.6
  Top Layer w35: C26.2@455,315 455,318.21 458.72,321.93 458.72,466.28 530,537.56
RX: J1.1 U7.26 | length 422.6
  Top Layer w8: v1(631,601) 637.67,601 644,607.33 U7.26
  Bottom Layer w8: J1.1 285,547 394,547 432,585 615,585 v1(631,601)
SWDCLK: P3.4 U7.23 | length 362.7
  Top Layer w8: v1(624,685) 700,685 713.87,671.13 U7.23
  Bottom Layer w8: P3.4 482,800 597,685 v1(624,685)
TX: J1.2 U7.25 | length 528.9
  Top Layer w8: v1(219,608) 600,608 615.07,623.07 U7.25
  Bottom Layer w8: J1.2 185,642 v1(219,608)
VBAT: C8.2 C10.2 P1.1 R5.2 U3.3 U5.1 | length 756.1
  Top Layer w15: U5.1 1518,850 1520.32,847.68 C10.2 R5.2 1652,715 1658.26,721.26 P1.1
  Bottom Layer w15: U3.3 1467.4,724 1470,726.6 C8.2 1701.26,760 P1.1
VBUS: C7.2 C13.2 D1.1 D2.1 R3.2 R6.2 U3.4 | length 614.6
  Top Layer w8: v1(1467.4,475) 1531.73,475 1546.73,490 R6.2 1607.28,510 1637.28,480 ; D1.1 D2.1 1637.28,480 ; C13.2 1661.54,521.25 1637.28,497 1637.28,480
  Bottom Layer w8: v1(1467.4,475) U3.4 1501,597.76 1501.08,597.68 C7.2 1535,574.28 1542.28,567 R3.2
XC1: C23.2 U7.34 X1.1 | length 393.1
  Top Layer w8: v1(628,476) 633.34,481.34 U7.34
  Bottom Layer w8: v1(628,476) 727,377 727,272 700,245 C23.2 698.54,263.54 X1.1
XC2: C17.2 U7.35 X1.3 | length 238.7
  Top Layer w8: v1(595,370) 630,405 630,445.59 650,465.59 U7.35
  Bottom Layer w8: v1(595,370) C17.2 656.22,357.76 641.46,343 X1.3
pads on no net: E1.2 J1.3 P3.6 P3.7 P3.8 P3.9 U1.1 U1.2 U1.3 U1.4 U1.5 U1.6 U1.7 U1.11 U1.12 U1.14 U1.15 U1.16 U1.17 U1.19 U1.21 U2.2 U2.3 U2.5 U2.9 U2.10 U2.11 U2.15 U4.6 U5.4 U7.2 U7.3 U7.4 U7.27 U7.28 U7.29 U7.41 U7.42 U7.43 U7.44 U8.7
copper on no net:
  other v2: 713.87,465.59 761.11,465.59 808.36,465.59 855.6,465.59 713.87,512.84 761.11,512.84 808.36,512.84 855.6,512.84 713.87,560.08 761.11,560.08 808.36,560.08 855.6,560.08 713.87,607.33 761.11,607.33 808.36,607.33 855.6,607.33

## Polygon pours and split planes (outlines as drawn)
GND on Bottom Layer "Bottom Layer-GND" (solid, pour order 4): 0,1080 1805,1080 1805,225 0,225
GND on Top Layer "Top Layer-GND" (solid, pour order 8): 0,1080 1805,1080 1805,225 0,225

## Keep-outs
Top Layer:
  region: 0,395 420,395 420,505.71 471.87,565 640,565 640,525 540,525 540,225 0,225
Bottom Layer:
  region: 0,395 420,395 420,505.71 471.87,565 640,565 640,525 540,525 540,225 0,225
